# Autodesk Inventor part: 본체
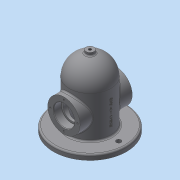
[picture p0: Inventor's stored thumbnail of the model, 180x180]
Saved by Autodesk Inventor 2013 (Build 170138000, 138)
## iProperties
Created: 2019-11
Part Number: 본체
Material: 일반
Document SubType Name: Modeling
Designer: Administrator
Density: 1 g/cm^3
Mass: 409.674 g
Surface Area: 883.25 cm^2
Volume: 409.674 cm^3
Author: Administrator
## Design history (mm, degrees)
sketch "스케치1"
  geometry: C1 r 70 at (0, 0); 1 further point
  constraints: 1 centre point, 1 coincident
  dimensions: "d0" = 140 diameter of C1
extrude "돌출1" new body sketch "스케치1" distance "d1" = 10; taper "d2" = 0 deg
sketch "스케치2"
  geometry: C1 r 70 at (0, 0) reference; C2 r 40 at (0, 0)
  constraints: 1 centre point, 1 coincident
  dimensions: "d3" = 80 diameter of C2
extrude "돌출2" join sketch "스케치2" distance "d4" = 120; taper "d5" = 0 deg
node "작업 평면1"
sketch "스케치3"
  geometry: C1 r 31 at (0, 50); 1 further point
  constraints: 1 centre point, 1 vertical alignment
  dimensions: "d7" = 62 diameter of C1; "d9" = 50 distance of point (0, 0) C1.centre
extrude "돌출3" join sketch "스케치3" stored distance "d10" = 80; taper "d11" = 0 deg
sketch "스케치4"
  geometry: L1 (-50, 81)-(-50, 19) reference; L2 (-50, 50)-(-35, 50); L3 (-35, 50)-(-35, 70); L4 (-35, 70)-(-50, 70); L5 (-50, 70)-(-50, 50); 1 further point
  constraints: 8 end point, 2 parallel, 1 horizontal, 1 midpoint, 1 perpendicular
  dimensions: "d12" = 15 distance of L3.end L4.end; "d14" = 40 diameter of L4 L2
revolve "회전1" sketch "스케치4" stored, may be unused: angle "d15" = 90 deg
sketch "스케치5"
  geometry: C1 r 20 at (0, 0) reference; C2 r 16.5 at (0, 0); 1 further point
  constraints: 1 centre point, 1 coincident
  dimensions: "d16" = 33 diameter of C2
extrude "돌출4" cut sketch "스케치5" stored distance "d17" = 80; taper "d18" = 0 deg
chamfer "모따기1" distance "d19" = 1; stored, may be unused: second distance "d20" = 2, angle "d21" = 45 deg
chamfer "모따기2" distance "d22" = 1; stored, may be unused: second distance "d23" = 2, angle "d24" = 45 deg
fillet "모깎기1" dims "d25" = 40
node "작업 평면2"
sketch "스케치6"
  geometry: C1 r 7.5 at (0, 0); 1 further point
  constraints: 1 centre point, 1 coincident
  dimensions: "d27" = 15 diameter of C1
extrude "돌출5" join sketch "스케치6" stored distance "d28" = 80; taper "d29" = 0 deg
sketch "스케치7"
  geometry: L1 (0, 0)-(-30, 0); L2 (-30, 0)-(-30, 90); L3 (0, 120)-(0, 120); L4 (0, 120)-(0, 0); A1 r 30 centre (0, 90) between (0, 120) and (-30, 90); 2 further points
  constraints: 8 end point, 2 coincident, 2 parallel, 2 point on circle, 2 point on line, 2 tangent, 1 centre point, 1 horizontal, 1 perpendicular
  dimensions: "d31" = 60 diameter of L2 L4; "d35" = 120 distance of L1.end point (-30, 120); "d36" = 30 radius of A1
revolve "회전2" sketch "스케치7" stored, may be unused: angle "d37" = 90 deg
sketch "스케치8"
  geometry: C1 r 7.5 at (0, 0) reference; 1 further point
  constraints: 1 coincident
hole "구멍1" sketch "스케치8" at (0, 0) diameter "d38" = 5.188; stored, may be unused: countersink angle "d42" = 90 deg, drill point angle "d44" = 0 deg; dims "d39" = 6, "d40" = 4, "d41" = 2, "d43" = 8
sketch "스케치9"
  geometry: C1 r 30 at (0, 0) reference; A1 r 55 centre (0, 0) between (-55, 0) and (55, 0)
  constraints: 2 coincident, 2 point on circle, 1 centre point
  dimensions: "d45" = 110 diameter of A1
hole "구멍2" sketch "스케치9" at (-55, 0), (55, 0) diameter "d46" = 9; stored, may be unused: countersink angle "d50" = 90 deg, drill point angle "d52" = 0 deg; dims "d47" = 6, "d48" = 4, "d49" = 2, "d51" = 10
fillet "모깎기2" dims "d53" = 3
fillet "모깎기3" dims "d54" = 3
fillet "모깎기4" dims "d55" = 3
fillet "모깎기5" dims "d56" = 3
sketch "스케치10" dims "d57" = 52
  geometry: C1 r 31 at (0, 0) reference; 3 further points
  constraints: 2 coincident, 1 vertical alignment, 2 other
hole "구멍3" sketch "스케치10" at (0, 26) diameter "d58" = 3.242; stored, may be unused: countersink angle "d62" = 90 deg, drill point angle "d64" = 118 deg; dims "d59" = 8, "d60" = 4, "d61" = 2, "d63" = 10
node "작업 평면3"
sketch "스케치11"
  geometry: L1 (-70, 0)-(70, 0) reference; 3 further points
  constraints: 1 midpoint, 1 vertical alignment, 1 other
  dimensions: "d69" = 50 distance from line of L1 point (0, 50)
feature "엠보싱1" sketch "스케치11" dims "d1" = 10, "d12" = 15, "d14" = 40, "d70" = 0.5, "d71" = 0
fillet "모깎기6" dims "d72" = 0.3
node "솔리드1"
mirror "대칭1"
mirror "대칭2"
pattern_circular "원형 패턴1" dims angle "d66" = 360 deg
mirror "대칭3"
other parameters: "d26" = 135
